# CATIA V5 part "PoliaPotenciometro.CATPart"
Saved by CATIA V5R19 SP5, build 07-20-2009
Part number: PeçaVeioPotenciometro
Bounding box of the stored display mesh (mm): x -4 to 4, y -27.464 to 27.464, z -27.464 to 27.464
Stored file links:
  Z:\UA\ATLAS\atlascar\ServoPiloto\dir\suportePotenciometro\V2\PoliaPotenciometro.CATPart
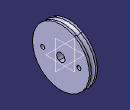
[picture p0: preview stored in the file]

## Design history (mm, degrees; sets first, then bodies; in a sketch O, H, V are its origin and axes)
Body1 (main body)
  Sketch1 on zx-plane, origin (0, 0, 0), H (-1, 0, 0), V (0, 0, 1)
    line L1 (-4, 4) -> (4, 4)
    point P2 (4, 4)
    point P3 (-4, 27.5)
    point P4 (-4, 27.5)
    line L2 (-4, 4) -> (-4, 27.5)
    point P5 (-2, 27.5)
    arc A1 centre (0, 27.5) radius 2 from (-2, 27.5) to (2, 27.5) ccw
    point P7 (0, 27.5)
    point P8 (4, 4)
    line L3 (2, 27.5) -> (4, 27.5)
    line L4 (4, 4) -> (4, 27.5)
    line L5 (-4, 27.5) -> (-2, 27.5)
    point P10 (-2, 27.5)
    distance H L1 = 4
    radius A1 = 2
    distance H P7 = 27.5
    distance L2 V = 4
    distance L4 L2 = 8
    horizontal: L1 H, L3 H
    vertical: L2 V, L4 V
    coincidence: P10 A1, L5 L3, P5 P10, P7 L3, P4 P3, P8 P2
    equidistance: L2 L4 P7
  Shaft1: profile Sketch1, axis Sketch1.H, angle 360
  Sketch2 on face of Shaft1 from Sketch1.L4, origin (-4, 0, 0), H (0, -1, 0), V (0, 0, 1)
    construction circle A1 centre (0, 0) radius 17.5
    circle A2 centre (17.5, 0) radius 2
    point P1 (17.5, 0)
    circle A3 centre (-17.5, 0) radius 2
    point P2 (-17.5, 0)
    radius A1 = 17.5
    radius A3 = 2
    radius A2 = 2
    coincidence: P2 A1, P1 A1
  Pocket1: profile Sketch2, direction (1, 0, 0), through (limit type 3)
